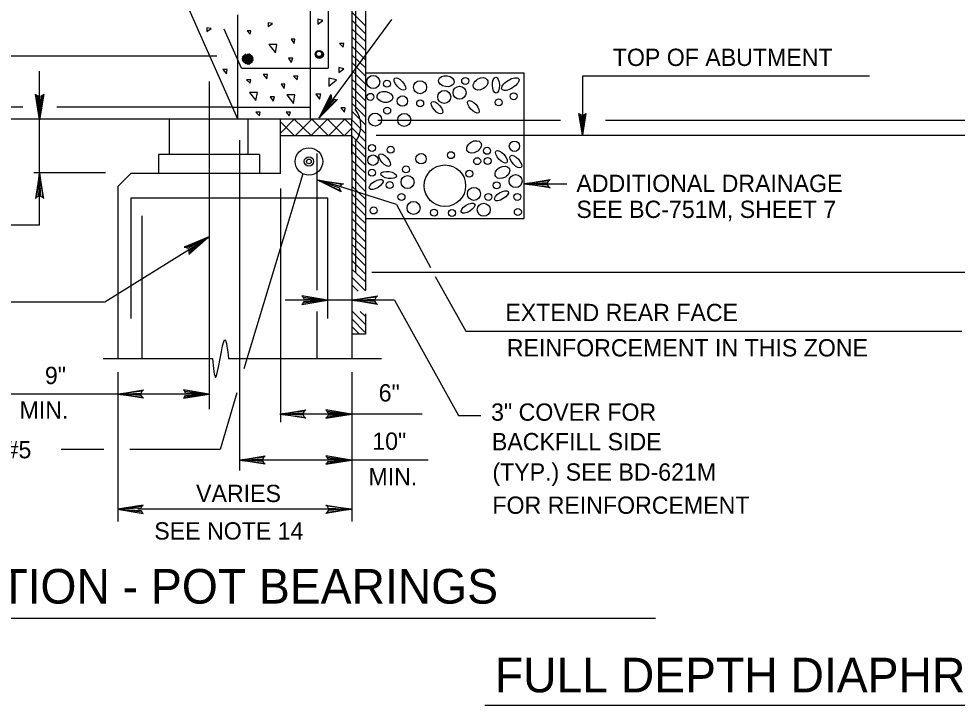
# Model space of a CAD drawing. Extents: x 640009 to 641706, y 298547 to 299735.
# Drawn here: x 640180 to 640342.7, y 299435.2 to 299554.2 of the extents above; entities that cross this region are included whole.
import ezdxf

# ---------------------------------------------------------------- set-up
doc = ezdxf.new("R2010")
doc.units = 0
doc.layers.add('1', color=7, linetype='Continuous')

msp = doc.modelspace()

# ---------------------------------------------------------------- linework, layer by layer
at = {"layer": '1'}
for p, q in [((640217.97, 299536.8), (640179.09, 299624.55)), ((640237.72, 299612.05), (640237.72, 299536.8)), ((640233.59, 299607.92), (640233.59, 299545.67)), ((640230.47, 299604.92), (640230.47, 299536.8)), ((640240.1, 299592.08), (640240.1, 299507.18)), ((640238.34, 299557.82), (640238.34, 299538.55)), ((640217.97, 299536.8), (640217.97, 299554.92)), ((640232.09, 299537.05), (640244.67, 299554.1)), ((640218.59, 299545.67), (640215.59, 299552.42)), ((640155.73, 299547.8), (640214.34, 299547.8)), ((640218.59, 299545.67), (640233.59, 299545.67)), ((640183.59, 299518.46), (640183.59, 299545.17)), ((640327.47, 299544.3), (640277.72, 299544.3)), ((640277.72, 299544.3), (640277.72, 299534.05)), ((640212.97, 299543.35), (640212.97, 299486.53)), ((640180.68, 299538.92), (640114.22, 299538.92)), ((640217.03, 299538.92), (640186.57, 299538.92)), ((640217.03, 299538.92), (640230.47, 299538.92)), ((640217.97, 299536.8), (640114.22, 299536.8)), ((640206.09, 299530.67), (640206.09, 299536.8)), ((640237.72, 299536.8), (640217.97, 299536.8)), ((640219.72, 299530.67), (640219.72, 299536.8)), ((640225.34, 299527.42), (640225.34, 299536.8)), ((640237.72, 299530.67), (640237.72, 299536.8)), ((640242.22, 299536.67), (640273.88, 299536.67)), ((640281.72, 299536.67), (640349.59, 299536.67)), ((640218.22, 299533.17), (640218.22, 299475.92)), ((640237.72, 299533.92), (640225.34, 299533.92)), ((640237.72, 299533.92), (640237.72, 299495.3)), ((640238.34, 299532.92), (640238.34, 299510.3)), ((640241.97, 299534.05), (640349.59, 299534.05)), ((640231.63, 299530.86), (640231.63, 299507.19)), ((640221.72, 299530.67), (640204.22, 299530.67)), ((640204.22, 299530.67), (640204.22, 299527.42)), ((640221.72, 299530.67), (640221.72, 299527.42)), ((640182.59, 299527.55), (640195, 299527.55)), ((640197.15, 299525.17), (640199.4, 299527.42)), ((640225.34, 299527.42), (640199.4, 299527.42)), ((640229.22, 299527.37), (640218.98, 299493.5)), ((640197.15, 299525.17), (640197.15, 299495.3)), ((640225.34, 299524.8), (640225.34, 299484.3)), ((640245.47, 299522.05), (640233.59, 299525.8)), ((640267.63, 299525.63), (640275.01, 299525.63)), ((640199.4, 299523.17), (640233.5, 299523.17)), ((640199.4, 299523.17), (640199.4, 299502.24)), ((640233.5, 299523.17), (640233.5, 299502.24)), ((640245.47, 299522.05), (640251.39, 299511.08)), ((640201.28, 299520.05), (640201.28, 299495.3)), ((640183.59, 299518.46), (640121.47, 299518.46)), ((640194.91, 299505.12), (640212.9, 299516.34)), ((640241.21, 299510.3), (640366.22, 299510.3)), ((640252.2, 299509.55), (640257.47, 299500.05)), ((640145.2, 299505.12), (640194.91, 299505.12)), ((640237.72, 299505.43), (640226.18, 299505.43)), ((640245.11, 299505.43), (640237.72, 299505.43)), ((640245.11, 299505.43), (640256.19, 299485.42)), ((640231.63, 299503.46), (640231.63, 299495.24)), ((640240.1, 299503.08), (640240.1, 299499.51)), ((640257.47, 299500.05), (640343.47, 299500.05)), ((640240.1, 299499.51), (640237.72, 299499.51)), ((640194.59, 299495.3), (640213.59, 299495.3)), ((640216.34, 299495.3), (640242.84, 299495.3)), ((640197.15, 299492.92), (640197.15, 299467.05)), ((640237.72, 299492.92), (640237.72, 299467.42)), ((640237.72, 299492.3), (640237.72, 299467.05)), ((640212.97, 299489.13), (640177.6, 299489.13)), ((640217.78, 299489.39), (640214.91, 299479.51)), ((640249.93, 299485.67), (640225.34, 299485.67)), ((640256.19, 299485.42), (640260.1, 299485.42)), ((640194.73, 299479.51), (640187.31, 299479.51)), ((640214.91, 299479.51), (640199.24, 299479.51)), ((640250.97, 299477.67), (640218.22, 299477.67)), ((640237.72, 299469.17), (640200.59, 299469.17)), ((640159.19, 299450.3), (640290.39, 299450.3)), ((640260.76, 299435.18), (640453.42, 299435.18))]:
    msp.add_line(p, q, dxfattribs=at)
for points in [[(640240.1, 299553.01), (640237.72, 299555.38)], [(640240.1, 299551.63), (640237.72, 299554.01)], [(640240.1, 299550.28), (640237.72, 299552.51)], [(640240.1, 299548.76), (640237.72, 299551.13)], [(640240.1, 299547.09), (640237.72, 299549.47)], [(640218.72, 299546.92), (640219.97, 299548.17)], [(640218.72, 299547.05), (640219.84, 299548.17)], [(640218.72, 299547.17), (640219.84, 299548.17)], [(640218.72, 299547.3), (640219.72, 299548.17)], [(640218.72, 299547.55), (640219.34, 299548.17)], [(640218.72, 299547.3), (640219.34, 299548.05)], [(640218.84, 299546.92), (640220.09, 299548.17)], [(640218.84, 299546.8), (640220.22, 299548.05)], [(640218.84, 299546.8), (640220.09, 299548.05)], [(640218.97, 299546.67), (640220.22, 299548.05)], [(640218.97, 299546.67), (640220.34, 299547.92)], [(640219.09, 299546.55), (640220.34, 299547.92)], [(640219.09, 299546.55), (640220.47, 299547.8)], [(640219.22, 299546.42), (640220.47, 299547.8)], [(640219.22, 299546.42), (640220.47, 299547.67)], [(640219.22, 299546.42), (640220.47, 299547.67)], [(640219.34, 299546.42), (640220.59, 299547.55)], [(640219.47, 299546.42), (640220.59, 299547.55)], [(640219.59, 299546.3), (640220.59, 299547.42)], [(640219.72, 299546.3), (640220.59, 299547.3)], [(640219.84, 299546.3), (640220.59, 299547.17)], [(640240.1, 299545.74), (640237.72, 299547.97)], [(640219.97, 299546.42), (640220.59, 299547.05)], [(640220.09, 299546.55), (640220.47, 299546.8)], [(640240.1, 299544.27), (640237.72, 299546.64)], [(640240.1, 299542.89), (640237.72, 299545.27)], [(640240.1, 299541.54), (640237.72, 299543.77)], [(640240.1, 299540.02), (640237.72, 299542.39)], [(640184.12, 299540.96), (640183.8, 299540.79), (640183.58, 299536.72), (640184.12, 299540.96), (640184.3, 299541.17), (640183.58, 299536.72), (640183.38, 299540.79), (640183.08, 299540.95), (640183.58, 299536.72), (640182.85, 299541.17), (640183.08, 299540.95)], [(640234.98, 299540.19), (640234.62, 299540.23), (640232.05, 299537.07), (640234.98, 299540.19), (640235.26, 299540.25), (640232.05, 299537.07), (640234.28, 299540.48), (640234.13, 299540.79), (640232.05, 299537.07), (640234.08, 299541.1), (640234.13, 299540.79)], [(640240.1, 299538.53), (640237.72, 299540.91)], [(640240.1, 299537.21), (640237.72, 299539.58)], [(640240.1, 299535.83), (640237.72, 299538.21)], [(640278.15, 299537.62), (640277.89, 299537.48), (640277.71, 299534.08), (640278.15, 299537.62), (640278.31, 299537.8), (640277.71, 299534.08), (640277.54, 299537.48), (640277.29, 299537.61), (640277.71, 299534.08), (640277.1, 299537.8), (640277.29, 299537.61)], [(640225.34, 299534.39), (640227.75, 299536.8)], [(640227.72, 299533.99), (640225.34, 299536.36)], [(640230.75, 299533.92), (640227.75, 299536.8)], [(640227.9, 299533.92), (640230.78, 299536.8)], [(640230.64, 299533.92), (640233.52, 299536.8)], [(640233.65, 299533.92), (640230.78, 299536.8)], [(640236.39, 299533.92), (640233.52, 299536.8)], [(640233.65, 299533.92), (640236.53, 299536.8)], [(640237.72, 299535.61), (640236.53, 299536.8)], [(640240.1, 299534.33), (640237.72, 299536.71)], [(640236.39, 299533.92), (640237.72, 299535.25)], [(640240.1, 299532.96), (640237.72, 299535.33)], [(640225.34, 299533.92), (640225.34, 299533.92)], [(640240.1, 299531.58), (640237.72, 299533.96)], [(640240.1, 299530.21), (640237.72, 299532.58)], [(640240.1, 299528.83), (640237.72, 299531.21)], [(640240.1, 299527.48), (640237.72, 299529.71)], [(640240.1, 299525.96), (640237.72, 299528.33)], [(640184.12, 299523.26), (640183.8, 299523.43), (640183.58, 299527.5), (640184.12, 299523.26), (640184.3, 299523.05), (640183.58, 299527.5), (640183.38, 299523.43), (640183.08, 299523.28), (640183.58, 299527.5), (640182.85, 299523.05), (640183.08, 299523.28)], [(640235.7, 299524.48), (640235.63, 299524.83), (640231.8, 299526.24), (640235.7, 299524.48), (640235.85, 299524.24), (640231.8, 299526.24), (640235.75, 299525.23), (640235.99, 299525.48), (640231.8, 299526.24), (640236.27, 299525.62), (640235.99, 299525.48)], [(640240.1, 299524.3), (640237.72, 299526.68)], [(640271.88, 299525.09), (640271.7, 299525.4), (640267.63, 299525.63), (640271.88, 299525.09), (640272.09, 299524.9), (640267.63, 299525.63), (640271.7, 299525.83), (640271.86, 299526.13), (640267.63, 299525.63), (640272.09, 299526.35), (640271.86, 299526.13)], [(640240.1, 299522.95), (640237.72, 299525.18)], [(640240.1, 299521.48), (640237.72, 299523.85)], [(640240.1, 299520.1), (640237.72, 299522.48)], [(640240.1, 299518.75), (640237.72, 299520.98)], [(640240.1, 299517.23), (640237.72, 299519.6)], [(640240.1, 299515.56), (640237.72, 299517.94)], [(640209.52, 299513.66), (640209.5, 299514.02), (640212.82, 299516.38), (640209.52, 299513.66), (640209.45, 299513.39), (640212.82, 299516.38), (640209.28, 299514.37), (640208.98, 299514.55), (640212.82, 299516.38), (640208.67, 299514.61), (640208.98, 299514.55)], [(640240.1, 299514.21), (640237.72, 299516.44)], [(640240.1, 299512.74), (640237.72, 299515.12)], [(640240.1, 299511.36), (640237.72, 299513.74)], [(640240.1, 299509.94), (640237.72, 299512.32)], [(640240.1, 299508.59), (640237.72, 299510.82)], [(640240.1, 299507.07), (640237.72, 299509.45)], [(640238.81, 299506.98), (640237.72, 299508.07)], [(640229.26, 299504.89), (640229.43, 299505.21), (640233.5, 299505.43), (640229.26, 299504.89), (640229.05, 299504.71), (640233.5, 299505.43), (640229.43, 299505.63), (640229.28, 299505.93), (640233.5, 299505.43), (640229.05, 299506.16), (640229.28, 299505.93)], [(640241.97, 299504.89), (640241.79, 299505.21), (640237.72, 299505.43), (640241.97, 299504.89), (640242.18, 299504.71), (640237.72, 299505.43), (640241.79, 299505.63), (640241.95, 299505.93), (640237.72, 299505.43), (640242.18, 299506.16), (640241.95, 299505.93)], [(640240.1, 299501.21), (640237.72, 299503.58)], [(640240.1, 299502.58), (640239.19, 299503.49)], [(640239.99, 299499.91), (640237.72, 299502.18)], [(640239.08, 299499.51), (640237.72, 299500.87)], [(640201.4, 299488.6), (640201.22, 299488.91), (640197.15, 299489.13), (640201.4, 299488.6), (640201.61, 299488.41), (640197.15, 299489.13), (640201.22, 299489.33), (640201.38, 299489.64), (640197.15, 299489.13), (640201.61, 299489.86), (640201.38, 299489.64)], [(640208.73, 299488.6), (640208.9, 299488.91), (640212.97, 299489.13), (640208.73, 299488.6), (640208.52, 299488.41), (640212.97, 299489.13), (640208.9, 299489.33), (640208.74, 299489.64), (640212.97, 299489.13), (640208.52, 299489.86), (640208.74, 299489.64)], [(640229.51, 299485.15), (640229.33, 299485.47), (640225.26, 299485.69), (640229.51, 299485.15), (640229.72, 299484.97), (640225.26, 299485.69), (640229.33, 299485.89), (640229.49, 299486.19), (640225.26, 299485.69), (640229.72, 299486.41), (640229.49, 299486.19)], [(640233.43, 299485.15), (640233.61, 299485.47), (640237.67, 299485.69), (640233.43, 299485.15), (640233.22, 299484.97), (640237.67, 299485.69), (640233.61, 299485.89), (640233.45, 299486.19), (640237.67, 299485.69), (640233.22, 299486.41), (640233.45, 299486.19)], [(640222.51, 299477.15), (640222.33, 299477.47), (640218.26, 299477.69), (640222.51, 299477.15), (640222.72, 299476.97), (640218.26, 299477.69), (640222.33, 299477.89), (640222.49, 299478.19), (640218.26, 299477.69), (640222.72, 299478.41), (640222.49, 299478.19)], [(640233.43, 299477.15), (640233.61, 299477.47), (640237.67, 299477.69), (640233.43, 299477.15), (640233.22, 299476.97), (640237.67, 299477.69), (640233.61, 299477.89), (640233.45, 299478.19), (640237.67, 299477.69), (640233.22, 299478.41), (640233.45, 299478.19)], [(640201.32, 299469.69), (640201.14, 299469.38), (640197.07, 299469.16), (640201.32, 299469.69), (640201.53, 299469.88), (640197.07, 299469.16), (640201.14, 299468.96), (640201.3, 299468.65), (640197.07, 299469.16), (640201.53, 299468.43), (640201.3, 299468.65)], [(640233.43, 299469.69), (640233.61, 299469.38), (640237.68, 299469.16), (640233.43, 299469.69), (640233.22, 299469.88), (640237.68, 299469.16), (640233.61, 299468.96), (640233.45, 299468.65), (640237.68, 299469.16), (640233.22, 299468.43), (640233.45, 299468.65)]]:
    msp.add_lwpolyline(points, dxfattribs=at)
for points in [[(640231.84, 299553.3), (640232.72, 299553.92), (640231.84, 299554.17)], [(640212.59, 299552.05), (640213.34, 299552.55), (640212.59, 299552.67)], [(640219.59, 299552.17), (640220.09, 299551.55), (640220.22, 299552.17)], [(640223.22, 299552.92), (640223.97, 299553.42), (640223.22, 299553.55)], [(640227.22, 299550.67), (640227.72, 299549.92), (640227.84, 299550.67)], [(640223.34, 299549.8), (640224.47, 299548.3), (640224.72, 299549.8)], [(640235.59, 299549.92), (640236.22, 299549.3), (640236.34, 299549.92)], [(640226.72, 299547.42), (640227.22, 299546.67), (640227.47, 299547.42)], [(640235.47, 299544.92), (640236.34, 299545.55), (640235.47, 299545.8)], [(640215.34, 299545.42), (640215.97, 299544.67), (640216.09, 299545.42)], [(640222.34, 299544.55), (640222.97, 299543.8), (640223.09, 299544.55)], [(640227.59, 299544.3), (640228.22, 299543.67), (640228.34, 299544.3)], [(640233.72, 299542.55), (640235.09, 299543.67), (640233.72, 299543.92)], [(640267.63, 299544.78), (640240.1, 299544.78), (640240.1, 299519.59), (640267.63, 299519.59)], [(640219.47, 299543.67), (640220.09, 299543.05), (640220.22, 299543.67)], [(640225.47, 299542.92), (640225.97, 299542.17), (640226.09, 299542.92)], [(640219.97, 299541.42), (640221.09, 299540.05), (640221.34, 299541.42)], [(640223.59, 299540.67), (640224.09, 299539.92), (640224.34, 299540.67)], [(640226.47, 299541.05), (640227.59, 299539.55), (640227.84, 299541.05)], [(640231.47, 299541.17), (640232.09, 299540.3), (640232.34, 299541.17)], [(640221.09, 299538.05), (640221.72, 299537.42), (640221.84, 299538.05)], [(640226.34, 299538.05), (640226.84, 299537.42), (640227.09, 299538.05)], [(640235.84, 299538.8), (640236.47, 299538.05), (640236.59, 299538.8)]]:
    msp.add_lwpolyline(points, close=True, dxfattribs=at)
for centre, radius in [((640231.98, 299548.09), 0.636), ((640232.1, 299548.04), 0.693), ((640232.04, 299548.15), 0.474), ((640241.43, 299543.27), 1.13), ((640257.38, 299543.45), 0.605), ((640243.8, 299542.97), 0.605), ((640249.55, 299542.37), 1.13), ((640256.4, 299541.41), 1.13), ((640240.95, 299540.69), 0.605), ((640246.49, 299539.97), 0.9), ((640253.74, 299540.67), 1.13), ((640265.8, 299540.8), 0.605), ((640249.57, 299539.55), 0.605), ((640263.19, 299539.73), 0.605), ((640241.76, 299536.74), 1.13), ((640243.85, 299538.3), 0.605), ((640246.81, 299536.68), 1.13), ((640265.92, 299532.13), 0.9), ((640230.29, 299529.49), 2.38), ((640241.22, 299531.82), 0.605), ((640244.46, 299531.52), 0.605), ((640249.72, 299529.96), 0.9), ((640254.9, 299530.58), 0.605), ((640261.17, 299531.34), 0.605), ((640230.29, 299529.49), 0.81), ((640230.29, 299529.49), 0.407), ((640241.39, 299529.71), 0.9), ((640259.46, 299529.54), 0.605), ((640261.27, 299529.57), 0.605), ((640241.22, 299527.54), 0.605), ((640247.11, 299528.11), 0.605), ((640253.86, 299525.29), 3.6), ((640258.08, 299527.37), 0.605), ((640244.27, 299525.39), 0.605), ((640247.38, 299525.92), 1.13), ((640262.83, 299525.35), 0.605), ((640266.13, 299526.08), 1.13), ((640258.9, 299523.87), 1.13), ((640246.33, 299523.33), 0.605), ((640261.41, 299523.33), 0.605), ((640266.4, 299523.33), 0.605), ((640241.49, 299520.99), 0.605), ((640248.42, 299521.42), 1.13), ((640251.99, 299520.61), 0.605), ((640255.09, 299520.55), 0.605), ((640260.59, 299521.11), 1.13), ((640266.51, 299520.72), 0.605)]:
    msp.add_circle(centre, radius, dxfattribs=at)
msp.add_arc((640234.84, 299535.72), 4.47, 321.0382, 38.9618, dxfattribs=at)
for centre, major_axis, ratio in [((640246.05, 299542.92), (0.91, -1.02), 0.438009), ((640254.11, 299543.41), (1.36, -0.2), 0.696126), ((640260.04, 299542.94), (1.17, 0.72), 0.696126), ((640262.71, 299542.71), (0.04, -1.37), 0.438009), ((640265.21, 299542.91), (1.46, 0.9), 0.438009), ((640243.45, 299540.68), (1.36, -0.2), 0.696126), ((640252.48, 299538.82), (0.91, -1.02), 0.438009), ((640258.81, 299538.96), (0.91, -1.02), 0.438009), ((640258.91, 299532.01), (1.17, 0.72), 0.696126), ((640243.41, 299529.73), (0.91, -1.02), 0.438009), ((640263.67, 299530.29), (0.91, -1.02), 0.438009), ((640266.16, 299529.46), (0.91, -1.02), 0.438009), ((640244.1, 299527.14), (1.36, -0.2), 0.438009), ((640263.84, 299527.6), (1.17, 0.72), 0.696126), ((640241.95, 299525.51), (1.17, 0.72), 0.438009), ((640263.66, 299523.55), (1.17, 0.72), 0.438009), ((640257.86, 299521.39), (1.17, 0.72), 0.438009)]:
    msp.add_ellipse(centre, major_axis=major_axis, ratio=ratio, dxfattribs=at)
msp.add_spline([(640213.59, 299495.3), (640214.09, 299492.05), (640215.72, 299498.55), (640216.34, 299495.3)], degree=3, dxfattribs=at)

# ---------------------------------------------------------------- texts
for s, height, p in [('TOP OF ABUTMENT', 3, (640282.97, 299546.05)), ('ADDITIONAL DRAINAGE', 3, (640276.66, 299524.19)), ('SEE BC-751M, SHEET 7', 3, (640276.66, 299519.69)), ('EXTEND REAR FACE', 3, (640264.34, 299501.8)), ('REINFORCEMENT IN THIS ZONE', 3, (640264.59, 299495.67)), ('9"', 3, (640184.5, 299490.88)), ('6"', 3, (640242.38, 299487.86)), ('MIN.', 3, (640180.11, 299484.86)), ('3" COVER FOR', 3, (640261.87, 299484.52)), ('10"', 3, (640241.27, 299479.48)), ('BACKFILL SIDE', 3, (640262.01, 299479.4)), ('1-#5', 3, (640174.12, 299478.01)), ('(TYP.) SEE BD-621M', 3, (640262.1, 299474.13)), ('MIN.', 3, (640240.6, 299473.31)), ('VARIES', 3, (640210.72, 299470.42)), ('FOR REINFORCEMENT', 3, (640262.1, 299468.38)), ('SEE NOTE 14', 3, (640203.47, 299463.92)), ('SECTION - POT BEARINGS', 6, (640160.1, 299452.81))]:
    msp.add_text(s, height=height, dxfattribs=at).set_placement(p)
msp.add_text('FULL DEPTH DIAPHRAGM AT ABUTMENT', height=6, rotation=360, dxfattribs=at).set_placement((640262.52, 299437.42))

doc.saveas('drawing.dxf')
